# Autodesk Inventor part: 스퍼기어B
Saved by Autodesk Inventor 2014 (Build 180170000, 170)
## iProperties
Created: 2024-05
Part Number: 스퍼기어B
Material: 일반
Document SubType Name: Modeling
Designer: dg
Density: 1 g/cm^3
Appearance: 기본값
Author: dg
Author: jhkim
Creation Date: 2024-05-10
Sending System: Autodesk Inventor 2025
Preprocessor: ST-DEVELOPER v20
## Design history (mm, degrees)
node "스퍼기어B1"
node "솔리드1"
node "기준1"
